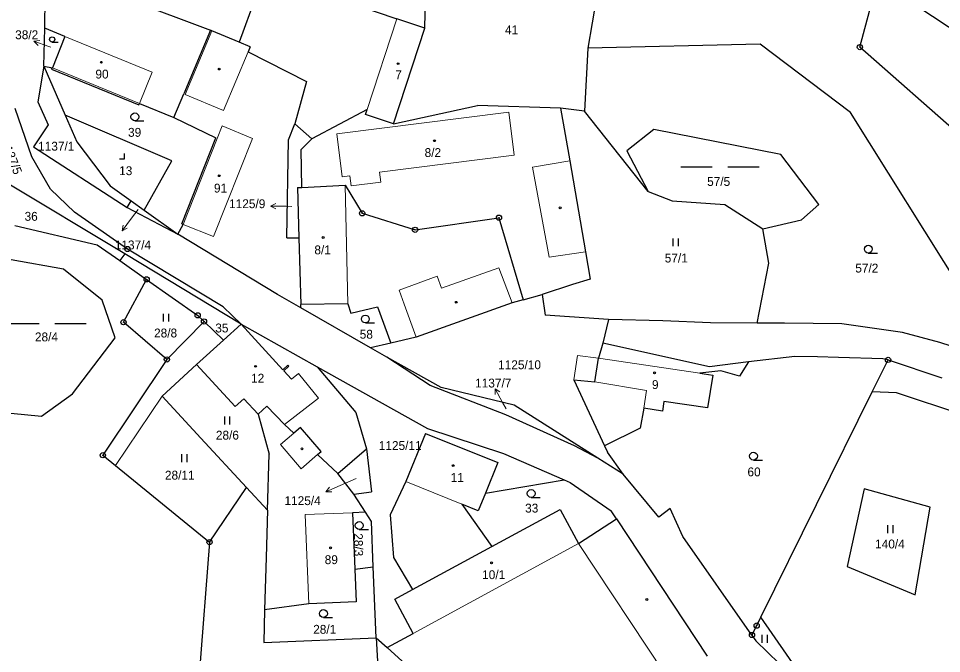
# Model space of a CAD drawing. Extents: x -765428 to -762163, y -1107632 to -1104975.
# Drawn here: x -764128.3 to -763951.2, y -1106215.1 to -1106093.3 of the extents above; entities that cross this region are included whole.
import ezdxf
from ezdxf.enums import TextEntityAlignment as Align

# ---------------------------------------------------------------- set-up
doc = ezdxf.new("R2010")
doc.units = 0
doc.header["$LTSCALE"] = 0.68
for name, color, linetype, lineweight in [('1', 7, 'Continuous', 25), ('13', 7, 'Continuous', 13), ('3', 7, 'Continuous', 25), ('4', 7, 'Continuous', 13), ('5', 7, 'Continuous', 25), ('7', 7, 'Continuous', 13), ('8', 7, 'Continuous', 25)]:
    doc.layers.add(name, color=color, linetype=linetype, lineweight=lineweight)
doc.layers.add('2', color=7, linetype='Continuous')

msp = doc.modelspace()

# ---------------------------------------------------------------- linework, layer by layer
at = {"layer": '1'}
for p, q in [((-764050.37, -1106095.15), (-764049.82, -1106074.07)), ((-764015.34, -1106077.09), (-764019.08, -1106098.98)), ((-764080.72, -1106083.55), (-764086.01, -1106097.83)), ((-764123.3, -1106095.13), (-764123.1, -1106085.59)), ((-764079.3, -1106085.3), (-764055.76, -1106093.38)), ((-763966.87, -1106098.78), (-763964.08, -1106088.41)), ((-764107.02, -1106089.63), (-764091.5, -1106095.53)), ((-763906.25, -1106123.86), (-763955.76, -1106091.07)), ((-764050.37, -1106095.15), (-764055.76, -1106093.38)), ((-764123.46, -1106102.41), (-764123.3, -1106095.13)), ((-764119.42, -1106096.72), (-764123.3, -1106095.13)), ((-764091.5, -1106095.53), (-764096.61, -1106107.75)), ((-764091.22, -1106095.65), (-764091.5, -1106095.53)), ((-764086.01, -1106097.83), (-764091.22, -1106095.65)), ((-764056.38, -1106113.48), (-764050.37, -1106095.15)), ((-764119.42, -1106096.72), (-764121.82, -1106102.77)), ((-764083.87, -1106098.72), (-764086.01, -1106097.83)), ((-763985.98, -1106098.23), (-764019.08, -1106098.98)), ((-763968.66, -1106111.35), (-763985.98, -1106098.23)), ((-764083.87, -1106098.72), (-764084.27, -1106099.68)), ((-764084.27, -1106099.68), (-764073.04, -1106105.4)), ((-764019.08, -1106098.98), (-764019.7, -1106111.07)), ((-763931.04, -1106130.43), (-763966.87, -1106098.78)), ((-764123.46, -1106102.41), (-764124.6, -1106109.28)), ((-764123.46, -1106102.41), (-764121.82, -1106102.77)), ((-764123.46, -1106102.41), (-764119.35, -1106111.82)), ((-764121.97, -1106103.04), (-764121.82, -1106102.77)), ((-764121.97, -1106103.04), (-764105.24, -1106109.87)), ((-764073.04, -1106105.4), (-764075.3, -1106113.49)), ((-764098.52, -1106112.31), (-764096.61, -1106107.75)), ((-764125.76, -1106119.84), (-764128.94, -1106110.55)), ((-764124.6, -1106109.28), (-764122.63, -1106113.67)), ((-764105.24, -1106109.87), (-764105.12, -1106109.6)), ((-764105.12, -1106109.6), (-764098.52, -1106112.31)), ((-764061.43, -1106110.74), (-764072.03, -1106116.35)), ((-764061.74, -1106111.69), (-764061.43, -1106110.74)), ((-764056.38, -1106113.48), (-764040.27, -1106110)), ((-764024.32, -1106110.51), (-764040.27, -1106110)), ((-764024.32, -1106110.51), (-764022.56, -1106120.59)), ((-764019.7, -1106111.07), (-764024.32, -1106110.51)), ((-764098.88, -1106120.62), (-764119.35, -1106111.82)), ((-764119.35, -1106111.82), (-764117.11, -1106116.94)), ((-764098.52, -1106112.31), (-764090.49, -1106116.2)), ((-764056.38, -1106113.48), (-764061.74, -1106111.69)), ((-764007.5, -1106126.49), (-764019.7, -1106111.07)), ((-763945.54, -1106148.31), (-763968.66, -1106111.35)), ((-764122.63, -1106113.67), (-764125.45, -1106117.91)), ((-764076.49, -1106116.6), (-764075.3, -1106113.49)), ((-764075.3, -1106113.49), (-764072.03, -1106116.35)), ((-764006.39, -1106114.57), (-764011.62, -1106118.65)), ((-763982.05, -1106119.36), (-764006.39, -1106114.57)), ((-764125.45, -1106117.91), (-764107.49, -1106129.53)), ((-764117.11, -1106116.94), (-764110.73, -1106125.38)), ((-764096.98, -1106132.7), (-764090.49, -1106116.2)), ((-764076.86, -1106135.36), (-764076.49, -1106116.6)), ((-764072.03, -1106116.35), (-764074.06, -1106118.41)), ((-764073.96, -1106125.7), (-764074.06, -1106118.41)), ((-764011.62, -1106118.65), (-764007.5, -1106126.49)), ((-763974.75, -1106128.96), (-763982.05, -1106119.36)), ((-764122.21, -1106126.01), (-764125.76, -1106119.84)), ((-764104.2, -1106130.06), (-764098.88, -1106120.62)), ((-764022.56, -1106120.59), (-764019.51, -1106138.05)), ((-764107.95, -1106138.44), (-764131.14, -1106124.47)), ((-764117.58, -1106130.44), (-764122.21, -1106126.01)), ((-764110.73, -1106125.38), (-764106.69, -1106128.28)), ((-764074.76, -1106125.74), (-764073.96, -1106125.7)), ((-764074.76, -1106125.74), (-764074.51, -1106135.36)), ((-764073.96, -1106125.7), (-764065.66, -1106125.28)), ((-764065.66, -1106125.28), (-764062.39, -1106130.66)), ((-764007.5, -1106126.49), (-764002.92, -1106128.26)), ((-764107.49, -1106129.53), (-764106.69, -1106128.28)), ((-764106.69, -1106128.28), (-764104.2, -1106130.06)), ((-764002.92, -1106128.26), (-763992.82, -1106128.96)), ((-764107.49, -1106129.53), (-764097.72, -1106134.69)), ((-764104.2, -1106130.06), (-764097.72, -1106134.69)), ((-763992.82, -1106128.96), (-763985.51, -1106133.62)), ((-763978.09, -1106131.93), (-763974.75, -1106128.96)), ((-764107.41, -1106137.52), (-764117.58, -1106130.44)), ((-764062.39, -1106130.66), (-764052.23, -1106133.82)), ((-764052.23, -1106133.82), (-764036.13, -1106131.51)), ((-764036.13, -1106131.51), (-764031.5, -1106147.25)), ((-763985.51, -1106133.62), (-763978.09, -1106131.93)), ((-764129.01, -1106132.99), (-764113.2, -1106136.69)), ((-764097.72, -1106134.69), (-764096.7, -1106132.81)), ((-764096.98, -1106132.7), (-764096.7, -1106132.81)), ((-763984.37, -1106140.22), (-763985.51, -1106133.62)), ((-764078.62, -1106146.25), (-764097.72, -1106134.69)), ((-764076.86, -1106135.36), (-764074.51, -1106135.36)), ((-764074.51, -1106135.36), (-764074.17, -1106148.18)), ((-764113.2, -1106136.69), (-764108.86, -1106139.74)), ((-764107.95, -1106138.44), (-764108.86, -1106139.74)), ((-764085.57, -1106151.93), (-764107.95, -1106138.44)), ((-764089.02, -1106148.62), (-764107.41, -1106137.52)), ((-764019.51, -1106138.05), (-764018.6, -1106143.27)), ((-764119.69, -1106141.37), (-764129.74, -1106139.56)), ((-764108.86, -1106139.74), (-764103.74, -1106143.34)), ((-763986.61, -1106151.73), (-763984.37, -1106140.22)), ((-764112.27, -1106147.31), (-764119.69, -1106141.37)), ((-764108.17, -1106151.55), (-764103.74, -1106143.34)), ((-764022, -1106144.33), (-764027.82, -1106146.23)), ((-764018.6, -1106143.27), (-764022, -1106144.33)), ((-764074.15, -1106148.82), (-764078.62, -1106146.25)), ((-764109.8, -1106154.56), (-764112.27, -1106147.31)), ((-764065.1, -1106148.03), (-764074.17, -1106148.18)), ((-764065.1, -1106148.03), (-764064.58, -1106149.84)), ((-764033.62, -1106147.81), (-764052.01, -1106154.43)), ((-764031.5, -1106147.25), (-764033.62, -1106147.81)), ((-764085.57, -1106151.93), (-764089.02, -1106148.62)), ((-764074.15, -1106148.82), (-764074.17, -1106148.18)), ((-764060.8, -1106156.5), (-764074.15, -1106148.82)), ((-764064.58, -1106149.84), (-764059.43, -1106148.6)), ((-764059.43, -1106148.6), (-764056.88, -1106155.58)), ((-764099.85, -1106158.69), (-764108.17, -1106151.55)), ((-764092.72, -1106151.41), (-764099.85, -1106158.69)), ((-764092.72, -1106151.41), (-764088.99, -1106155)), ((-764015.1, -1106151.04), (-764027.28, -1106150.23)), ((-764015.1, -1106151.04), (-764016.18, -1106155.6)), ((-764004.67, -1106151.3), (-764015.1, -1106151.04)), ((-763995.54, -1106151.69), (-764004.67, -1106151.3)), ((-764085.57, -1106151.93), (-764088.99, -1106155)), ((-764085.57, -1106151.93), (-764071, -1106160.09)), ((-763986.61, -1106151.73), (-763995.54, -1106151.69)), ((-763981.33, -1106151.76), (-763986.61, -1106151.73)), ((-763970.31, -1106151.89), (-763981.33, -1106151.76)), ((-763958.67, -1106153.53), (-763970.31, -1106151.89)), ((-764117.96, -1106165.27), (-764109.8, -1106154.56)), ((-764088.99, -1106155), (-764094.19, -1106159.67)), ((-764052.01, -1106154.43), (-764056.88, -1106155.58)), ((-763951.53, -1106155.43), (-763958.67, -1106153.53)), ((-764056.88, -1106155.58), (-764060.8, -1106156.5)), ((-764057.64, -1106158.26), (-764060.8, -1106156.5)), ((-764016.18, -1106155.6), (-764017.04, -1106158.48)), ((-763995.71, -1106160.13), (-764016.18, -1106155.6)), ((-763949.38, -1106156.14), (-763951.53, -1106155.43)), ((-764049.35, -1106163.67), (-764057.64, -1106158.26)), ((-764047.19, -1106164.07), (-764057.64, -1106158.26)), ((-764017.75, -1106163.01), (-764017.04, -1106158.48)), ((-763979.34, -1106158.11), (-763988.24, -1106159.14)), ((-763974.98, -1106158.19), (-763979.34, -1106158.11)), ((-763970.95, -1106158.35), (-763974.98, -1106158.19)), ((-763962.49, -1106158.57), (-763970.95, -1106158.35)), ((-763961.47, -1106158.78), (-763962.49, -1106158.57)), ((-764099.85, -1106158.69), (-764112.14, -1106177.06)), ((-764094.19, -1106159.67), (-764100.77, -1106165.75)), ((-764094.19, -1106159.67), (-764086.73, -1106167.7)), ((-764071, -1106160.09), (-764049.83, -1106171.94)), ((-764071, -1106160.09), (-764063.6, -1106168.89)), ((-763988.24, -1106159.14), (-763995.71, -1106160.13)), ((-763988.24, -1106159.14), (-763989.95, -1106161.93)), ((-763964.5, -1106164.9), (-763961.47, -1106158.78)), ((-763961.47, -1106158.78), (-763951.15, -1106162.22)), ((-763993.56, -1106160.87), (-763997.61, -1106161.34)), ((-763997.61, -1106161.34), (-763995.12, -1106161.71)), ((-763995.12, -1106161.71), (-763996.09, -1106168)), ((-763989.95, -1106161.93), (-763993.56, -1106160.87)), ((-764034.81, -1106169.33), (-764049.35, -1106163.67)), ((-764021.78, -1106162.63), (-764017.75, -1106163.01)), ((-764021.78, -1106162.63), (-764015.87, -1106175.24)), ((-764123.89, -1106169.55), (-764117.96, -1106165.27)), ((-764093.33, -1106173.79), (-764100.77, -1106165.75)), ((-764033.21, -1106167.49), (-764047.19, -1106164.07)), ((-763985.89, -1106208.16), (-763964.5, -1106164.9)), ((-763959.86, -1106165.13), (-763964.5, -1106164.9)), ((-763940.65, -1106171.48), (-763959.86, -1106165.13)), ((-764086.73, -1106167.7), (-764085.11, -1106166.25)), ((-764085.11, -1106166.25), (-764082.32, -1106169.19)), ((-764017.17, -1106177.64), (-764033.21, -1106167.49)), ((-764004.48, -1106166.79), (-764004.75, -1106168.61)), ((-763996.09, -1106168), (-764004.48, -1106166.79)), ((-764129.82, -1106168.98), (-764123.89, -1106169.55)), ((-764082.32, -1106169.19), (-764080.66, -1106167.63)), ((-764082.32, -1106169.19), (-764080.25, -1106176.86)), ((-764080.66, -1106167.63), (-764077.29, -1106171.2)), ((-764063.6, -1106168.89), (-764061.53, -1106175.85)), ((-764008.33, -1106168.01), (-764009.02, -1106171.87)), ((-764004.75, -1106168.61), (-764008.33, -1106168.01)), ((-764021.62, -1106175.27), (-764034.81, -1106169.33)), ((-764075.5, -1106172.83), (-764077.29, -1106171.2)), ((-764074.24, -1106171.75), (-764075.5, -1106172.83)), ((-764070.25, -1106176.33), (-764074.24, -1106171.75)), ((-764049.83, -1106171.94), (-764035.26, -1106176.72)), ((-764009.02, -1106171.87), (-764015.87, -1106175.24)), ((-764093.33, -1106173.79), (-764084.57, -1106183.25)), ((-764050.2, -1106172.9), (-764054.02, -1106182.09)), ((-764050.2, -1106172.9), (-764036.34, -1106178.48)), ((-764070.98, -1106176.96), (-764070.25, -1106176.33)), ((-764067.05, -1106180.55), (-764061.53, -1106175.85)), ((-764061.53, -1106175.85), (-764060.62, -1106184.09)), ((-764017.17, -1106177.64), (-764021.62, -1106175.27)), ((-764015.87, -1106175.24), (-764015.28, -1106176.49)), ((-764112.14, -1106177.06), (-764091.66, -1106193.73)), ((-764080.57, -1106187.58), (-764080.25, -1106176.86)), ((-764067.05, -1106180.55), (-764070.98, -1106176.96)), ((-764035.26, -1106176.72), (-764023.59, -1106181.79)), ((-764012.3, -1106180.72), (-764017.17, -1106177.64)), ((-764012.3, -1106180.72), (-764015.28, -1106176.49)), ((-764036.34, -1106178.48), (-764038.73, -1106184.32)), ((-764064, -1106184.51), (-764067.05, -1106180.55)), ((-764005.44, -1106188.93), (-764012.3, -1106180.72)), ((-764091.66, -1106193.73), (-764084.57, -1106183.25)), ((-764084.57, -1106183.25), (-764080.57, -1106187.58)), ((-764054.02, -1106182.09), (-764057.02, -1106188.51)), ((-764038.73, -1106184.32), (-764023.59, -1106181.79)), ((-764023.59, -1106181.79), (-764022.47, -1106182.27)), ((-764022.47, -1106182.27), (-764014.6, -1106187.72)), ((-764064, -1106184.51), (-764060.62, -1106184.09)), ((-764061.75, -1106188), (-764064, -1106184.51)), ((-764038.73, -1106184.32), (-764040.13, -1106187.75)), ((-763966.06, -1106183.49), (-763969.34, -1106198.42)), ((-763953.38, -1106187.03), (-763966.06, -1106183.49)), ((-764040.13, -1106187.75), (-764043.26, -1106186.47)), ((-764043.26, -1106186.47), (-764037.47, -1106194.57)), ((-764080.57, -1106187.58), (-764080.79, -1106196.66)), ((-764061.75, -1106188), (-764064.22, -1106188.1)), ((-764064.22, -1106188.1), (-764063.76, -1106198.95)), ((-764060.6, -1106189.8), (-764061.75, -1106188)), ((-764057.02, -1106188.51), (-764056.37, -1106196.71)), ((-764037.47, -1106194.57), (-764024.41, -1106187.5)), ((-764024.41, -1106187.5), (-764020.85, -1106193.99)), ((-764013.58, -1106189.27), (-764014.6, -1106187.72)), ((-764003.3, -1106187.28), (-764005.44, -1106188.93)), ((-764000.83, -1106192.66), (-764003.3, -1106187.28)), ((-763956.27, -1106203.86), (-763953.38, -1106187.03)), ((-764060.24, -1106198.47), (-764060.6, -1106189.8)), ((-764020.85, -1106193.99), (-764013.58, -1106189.27)), ((-764013.58, -1106189.27), (-763996.21, -1106215.6)), ((-764091.66, -1106193.73), (-764094.55, -1106230.53)), ((-763987.58, -1106211.56), (-764000.83, -1106192.66)), ((-764052.74, -1106202.83), (-764037.47, -1106194.57)), ((-764080.79, -1106196.66), (-764081.09, -1106206.7)), ((-764056.37, -1106196.71), (-764052.74, -1106202.83)), ((-764063.76, -1106198.95), (-764060.24, -1106198.47)), ((-764063.76, -1106198.95), (-764063.5, -1106205.22)), ((-764059.68, -1106212.1), (-764060.24, -1106198.47)), ((-763969.34, -1106198.42), (-763956.27, -1106203.86)), ((-764056.13, -1106204.66), (-764052.74, -1106202.83)), ((-764052.58, -1106211.24), (-764056.13, -1106204.66)), ((-764072.64, -1106205.57), (-764081.09, -1106206.7)), ((-764063.5, -1106205.22), (-764072.64, -1106205.57)), ((-764081.09, -1106206.7), (-764081.28, -1106212.99)), ((-763986.68, -1106209.75), (-763985.89, -1106208.16)), ((-763976.99, -1106220.91), (-763985.89, -1106208.16)), ((-763987.58, -1106211.56), (-763986.68, -1106209.75)), ((-764057.6, -1106213.97), (-764052.58, -1106211.24)), ((-763987.58, -1106211.56), (-763986.82, -1106212.65)), ((-764081.28, -1106212.99), (-764059.68, -1106212.1)), ((-764059.68, -1106212.1), (-764057.6, -1106213.97)), ((-764059.68, -1106212.1), (-764059.33, -1106218.86)), ((-763986.82, -1106212.65), (-763977.72, -1106221.48)), ((-764057.6, -1106213.97), (-764046.6, -1106223.82))]:
    msp.add_line(p, q, dxfattribs=at)
for points in [[(-764103.74, -1106143.34), (-764093.94, -1106150.24), (-764092.72, -1106151.41)], [(-764031.5, -1106147.25), (-764027.82, -1106146.23), (-764027.28, -1106150.23)]]:
    msp.add_lwpolyline(points, dxfattribs=at)
at = {"layer": '13'}
msp.add_lwpolyline([(-764112.14, -1106177.06), (-764109.69, -1106179.05), (-764100.77, -1106165.75), (-764094.19, -1106159.67), (-764088.99, -1106155), (-764092.72, -1106151.41), (-764099.85, -1106158.69)], close=True, dxfattribs=at)
at = {"layer": '3'}
for p, q in [((-764121.865, -1106097.82), (-764120.693, -1106097.82)), ((-764105.993, -1106112.91), (-764104.243, -1106112.91)), ((-764001.209, -1106121.76), (-763995.209, -1106121.76)), ((-763992.209, -1106121.76), (-763986.209, -1106121.76)), ((-764002.711, -1106136.97), (-764002.711, -1106135.47)), ((-764001.71, -1106136.97), (-764001.71, -1106135.47)), ((-763965.263, -1106138.28), (-763963.513, -1106138.28)), ((-764100.481, -1106151.42), (-764100.481, -1106149.92)), ((-764099.48, -1106151.42), (-764099.48, -1106149.92)), ((-764130.329, -1106151.83), (-764124.329, -1106151.83)), ((-764121.329, -1106151.83), (-764115.329, -1106151.83)), ((-764061.763, -1106151.7), (-764060.013, -1106151.7)), ((-764088.751, -1106171.17), (-764088.751, -1106169.67)), ((-764087.75, -1106171.17), (-764087.75, -1106169.67)), ((-764096.951, -1106178.37), (-764096.951, -1106176.87)), ((-764095.95, -1106178.37), (-764095.95, -1106176.87)), ((-763987.303, -1106177.99), (-763985.553, -1106177.99)), ((-764029.953, -1106185.16), (-764028.203, -1106185.16)), ((-763961.491, -1106192), (-763961.491, -1106190.5)), ((-763960.49, -1106192), (-763960.49, -1106190.5)), ((-764062.943, -1106191.3), (-764061.193, -1106191.3)), ((-764069.813, -1106208.19), (-764068.063, -1106208.19)), ((-763985.631, -1106213.04), (-763985.631, -1106211.54)), ((-763984.63, -1106213.04), (-763984.63, -1106211.54))]:
    msp.add_line(p, q, dxfattribs=at)
msp.add_lwpolyline([(-764108.961, -1106120.19), (-764107.96, -1106120.19), (-764107.96, -1106119.19)], dxfattribs=at)
for centre, radius in [((-764121.8652, -1106097.3174), 0.5025), ((-764105.9929, -1106112.1598), 0.75), ((-763965.2629, -1106137.5298), 0.75), ((-764061.7629, -1106150.9498), 0.75), ((-763987.3029, -1106177.2398), 0.75), ((-764029.9529, -1106184.4098), 0.75), ((-764062.9429, -1106190.5498), 0.75), ((-764069.8129, -1106207.4398), 0.75)]:
    msp.add_circle(centre, radius, dxfattribs=at)
at = {"layer": '4'}
for p, q in [((-764061.43, -1106110.74), (-764055.76, -1106093.38)), ((-764119.42, -1106096.72), (-764102.66, -1106103.57)), ((-764084.27, -1106099.68), (-764088.98, -1106110.94)), ((-764105.12, -1106109.6), (-764121.82, -1106102.77)), ((-764102.66, -1106103.57), (-764105.12, -1106109.6)), ((-764034.25, -1106111.27), (-764067.27, -1106115.43)), ((-764034.25, -1106111.27), (-764033.21, -1106119.52)), ((-764090.22, -1106116.33), (-764089.26, -1106113.9)), ((-764083.43, -1106116.29), (-764089.26, -1106113.9)), ((-764067.27, -1106115.43), (-764066.23, -1106123.68)), ((-764090.22, -1106116.33), (-764096.7, -1106132.81)), ((-764033.21, -1106119.52), (-764059.06, -1106122.78)), ((-764022.56, -1106120.59), (-764029.69, -1106121.84)), ((-764058.81, -1106124.72), (-764059.06, -1106122.78)), ((-764029.69, -1106121.84), (-764026.47, -1106139.08)), ((-764064.74, -1106123.49), (-764066.23, -1106123.68)), ((-764064.74, -1106123.49), (-764064.5, -1106125.4)), ((-764064.5, -1106125.4), (-764058.81, -1106124.72)), ((-764065.66, -1106125.28), (-764065.1, -1106148.03)), ((-764019.51, -1106138.05), (-764026.47, -1106139.08)), ((-764047.98, -1106142.72), (-764055.3, -1106145.39)), ((-764047.13, -1106145.05), (-764047.98, -1106142.72)), ((-764036.16, -1106141.1), (-764047.13, -1106145.05)), ((-764033.62, -1106147.81), (-764036.16, -1106141.1)), ((-764055.3, -1106145.39), (-764054.32, -1106148.08)), ((-764052.01, -1106154.43), (-764054.32, -1106148.08)), ((-764077.61, -1106160.67), (-764085.57, -1106151.93)), ((-764021.04, -1106157.91), (-764021.78, -1106162.63)), ((-764017.04, -1106158.48), (-764021.04, -1106157.91)), ((-763997.61, -1106161.34), (-764017.04, -1106158.48)), ((-764076.63, -1106159.78), (-764077.61, -1106160.67)), ((-764077.42, -1106160.88), (-764076.43, -1106159.97)), ((-764076.43, -1106159.97), (-764076.63, -1106159.78)), ((-764075.97, -1106162.46), (-764077.42, -1106160.88)), ((-764074.62, -1106161.39), (-764075.97, -1106162.46)), ((-764070.75, -1106166.11), (-764074.62, -1106161.39)), ((-764007.81, -1106164.66), (-764017.75, -1106163.01)), ((-764008.33, -1106168.01), (-764007.81, -1106164.66)), ((-764077.29, -1106171.2), (-764070.75, -1106166.11)), ((-764075.5, -1106172.83), (-764078.07, -1106175.04)), ((-764078.07, -1106175.04), (-764074.11, -1106179.65)), ((-764074.11, -1106179.65), (-764070.98, -1106176.96)), ((-764043.26, -1106186.47), (-764054.02, -1106182.09)), ((-764073.29, -1106188.45), (-764064.22, -1106188.1)), ((-764073.29, -1106188.45), (-764072.64, -1106205.57)), ((-764020.85, -1106193.99), (-764052.58, -1106211.24)), ((-764004.44, -1106218.82), (-764020.85, -1106193.99))]:
    msp.add_line(p, q, dxfattribs=at)
for points in [[(-764091.22, -1106095.65), (-764096.33, -1106107.87), (-764088.98, -1106110.94)], [(-764083.43, -1106116.29), (-764090.91, -1106135.13), (-764096.7, -1106132.81)]]:
    msp.add_lwpolyline(points, dxfattribs=at)
at = {"layer": '5'}
for centre in [(-764112.4268, -1106101.6892), (-764055.4968, -1106101.9592), (-764089.7968, -1106102.9992), (-764048.5068, -1106116.7392), (-764089.7968, -1106123.4492), (-764024.3768, -1106129.5992), (-764069.8568, -1106135.2992), (-764044.3268, -1106147.7292), (-764082.8268, -1106160.0192), (-764006.2668, -1106161.2492), (-764073.9268, -1106175.8492), (-764044.9168, -1106179.0592), (-764068.4368, -1106194.8292), (-764037.5368, -1106197.7092), (-764007.7468, -1106204.7392)]:
    msp.add_circle(centre, 0.175, dxfattribs=at)
at = {"layer": '7'}
for p, q in [((-764125.357, -1106097.673), (-764124.574, -1106098.472)), ((-764079.961, -1106129.268), (-764078.968, -1106129.786)), ((-764108.456, -1106134.017), (-764107.453, -1106133.518)), ((-764036.885, -1106164.305), (-764036.837, -1106165.424)), ((-764069.332, -1106184.071), (-764068.213, -1106184.121))]:
    msp.add_line(p, q, dxfattribs=at)
for points in [[(-764122.14, -1106098.78), (-764122.52, -1106098.65), (-764125.357, -1106097.673), (-764124.248, -1106097.526)], [(-764105.37, -1106129.95), (-764106.65, -1106131.62), (-764108.456, -1106134.017), (-764108.253, -1106132.916)], [(-764075.89, -1106129.34), (-764076.96, -1106129.32), (-764079.961, -1106129.268), (-764078.95, -1106128.784)], [(-764034.73, -1106168.19), (-764035.43, -1106166.93), (-764036.885, -1106164.305), (-764035.961, -1106164.938)], [(-764063.56, -1106181.51), (-764066.59, -1106182.85), (-764069.332, -1106184.071), (-764068.62, -1106183.206)]]:
    msp.add_lwpolyline(points, dxfattribs=at)
at = {"layer": '8'}
for centre, radius in [((-763966.87, -1106098.7799), 0.5), ((-763966.87, -1106098.7799), 0.0303), ((-764062.39, -1106130.6599), 0.5), ((-764062.39, -1106130.6599), 0.0303), ((-764036.13, -1106131.5099), 0.5), ((-764036.13, -1106131.5099), 0.0303), ((-764052.23, -1106133.8199), 0.5), ((-764052.23, -1106133.8199), 0.0303), ((-764107.41, -1106137.5199), 0.5), ((-764107.41, -1106137.5199), 0.0303), ((-764103.74, -1106143.3399), 0.5), ((-764103.74, -1106143.3399), 0.0303), ((-764093.94, -1106150.2399), 0.5), ((-764108.17, -1106151.5499), 0.5), ((-764108.17, -1106151.5499), 0.0303), ((-764093.94, -1106150.2399), 0.0303), ((-764092.72, -1106151.4099), 0.5), ((-764092.72, -1106151.4099), 0.0303), ((-764099.85, -1106158.6899), 0.5), ((-764099.85, -1106158.6899), 0.0303), ((-763961.47, -1106158.7799), 0.5), ((-763961.47, -1106158.7799), 0.0303), ((-764112.14, -1106177.0599), 0.5), ((-764112.14, -1106177.0599), 0.0303), ((-764091.66, -1106193.7299), 0.5), ((-764091.66, -1106193.7299), 0.0303), ((-763986.68, -1106209.7499), 0.5), ((-763986.68, -1106209.7499), 0.0303), ((-763987.58, -1106211.5599), 0.5), ((-763987.58, -1106211.5599), 0.0303)]:
    msp.add_circle(centre, radius, dxfattribs=at)

# ---------------------------------------------------------------- texts
at = {"layer": '2'}
for s, p in [('41', (-764034.98, -1106096.325)), ('90', (-764113.56, -1106104.815)), ('7', (-764056.03, -1106104.935)), ('39', (-764107.3, -1106115.985)), ('8/2', (-764050.4, -1106119.865)), ('13', (-764109.01, -1106123.345)), ('91', (-764090.82, -1106126.675)), ('57/5', (-763996.19, -1106125.415)), ('36', (-764127.16, -1106132.095)), ('8/1', (-764071.55, -1106138.535)), ('57/1', (-764004.32, -1106140.095)), ('57/2', (-763967.76, -1106142.025)), ('58', (-764062.85, -1106154.715)), ('28/4', (-764125.17, -1106155.225)), ('1125/10', (-764036.29, -1106160.565)), ('12', (-764083.69, -1106163.145)), ('9', (-764006.77, -1106164.375)), ('28/6', (-764090.45, -1106174.075)), ('1125/11', (-764059.19, -1106176.065)), ('60', (-763988.45, -1106181.115)), ('11', (-764045.41, -1106182.185)), ('33', (-764031.11, -1106188.065)), ('89', (-764069.57, -1106197.955)), ('10/1', (-764039.36, -1106200.835)), ('28/1', (-764071.78, -1106211.315))]:
    msp.add_text(s, height=1.7, dxfattribs=at).set_placement(p)
for s, p in [('38/2', (-764124.539, -1106097.265)), ('1125/9', (-764080.959, -1106129.675)), ('1137/4', (-764102.889, -1106137.585)), ('1125/4', (-764070.329, -1106186.635))]:
    msp.add_text(s, height=1.7, dxfattribs=at).set_placement(p, align=Align.RIGHT)
msp.add_text('1137/5', height=1.7, rotation=292, dxfattribs=at).set_placement((-764130.448, -1106120.1711), align=Align.CENTER)
for s, p in [('1137/1', (-764121.08, -1106118.645)), ('28/8', (-764100.099, -1106154.475)), ('35', (-764089.299, -1106153.515)), ('1137/7', (-764037.23, -1106164.075)), ('28/11', (-764097.38, -1106181.745)), ('140/4', (-763961.11, -1106194.945))]:
    msp.add_text(s, height=1.7, dxfattribs=at).set_placement(p, align=Align.CENTER)
msp.add_text('28/3', height=1.7, rotation=271, dxfattribs=at).set_placement((-764063.974, -1106192.047))

doc.saveas('drawing.dxf')
